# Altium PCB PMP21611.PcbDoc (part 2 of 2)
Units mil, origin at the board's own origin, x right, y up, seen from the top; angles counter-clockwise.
Board outline 4470 x 3145 mil, 4 copper layers (Top Layer, Signal Layer 1, Signal Layer 2, Bottom Layer), stack 60.6 mil thick; 95 components, 31 nets, 221 pads, 370 vias.
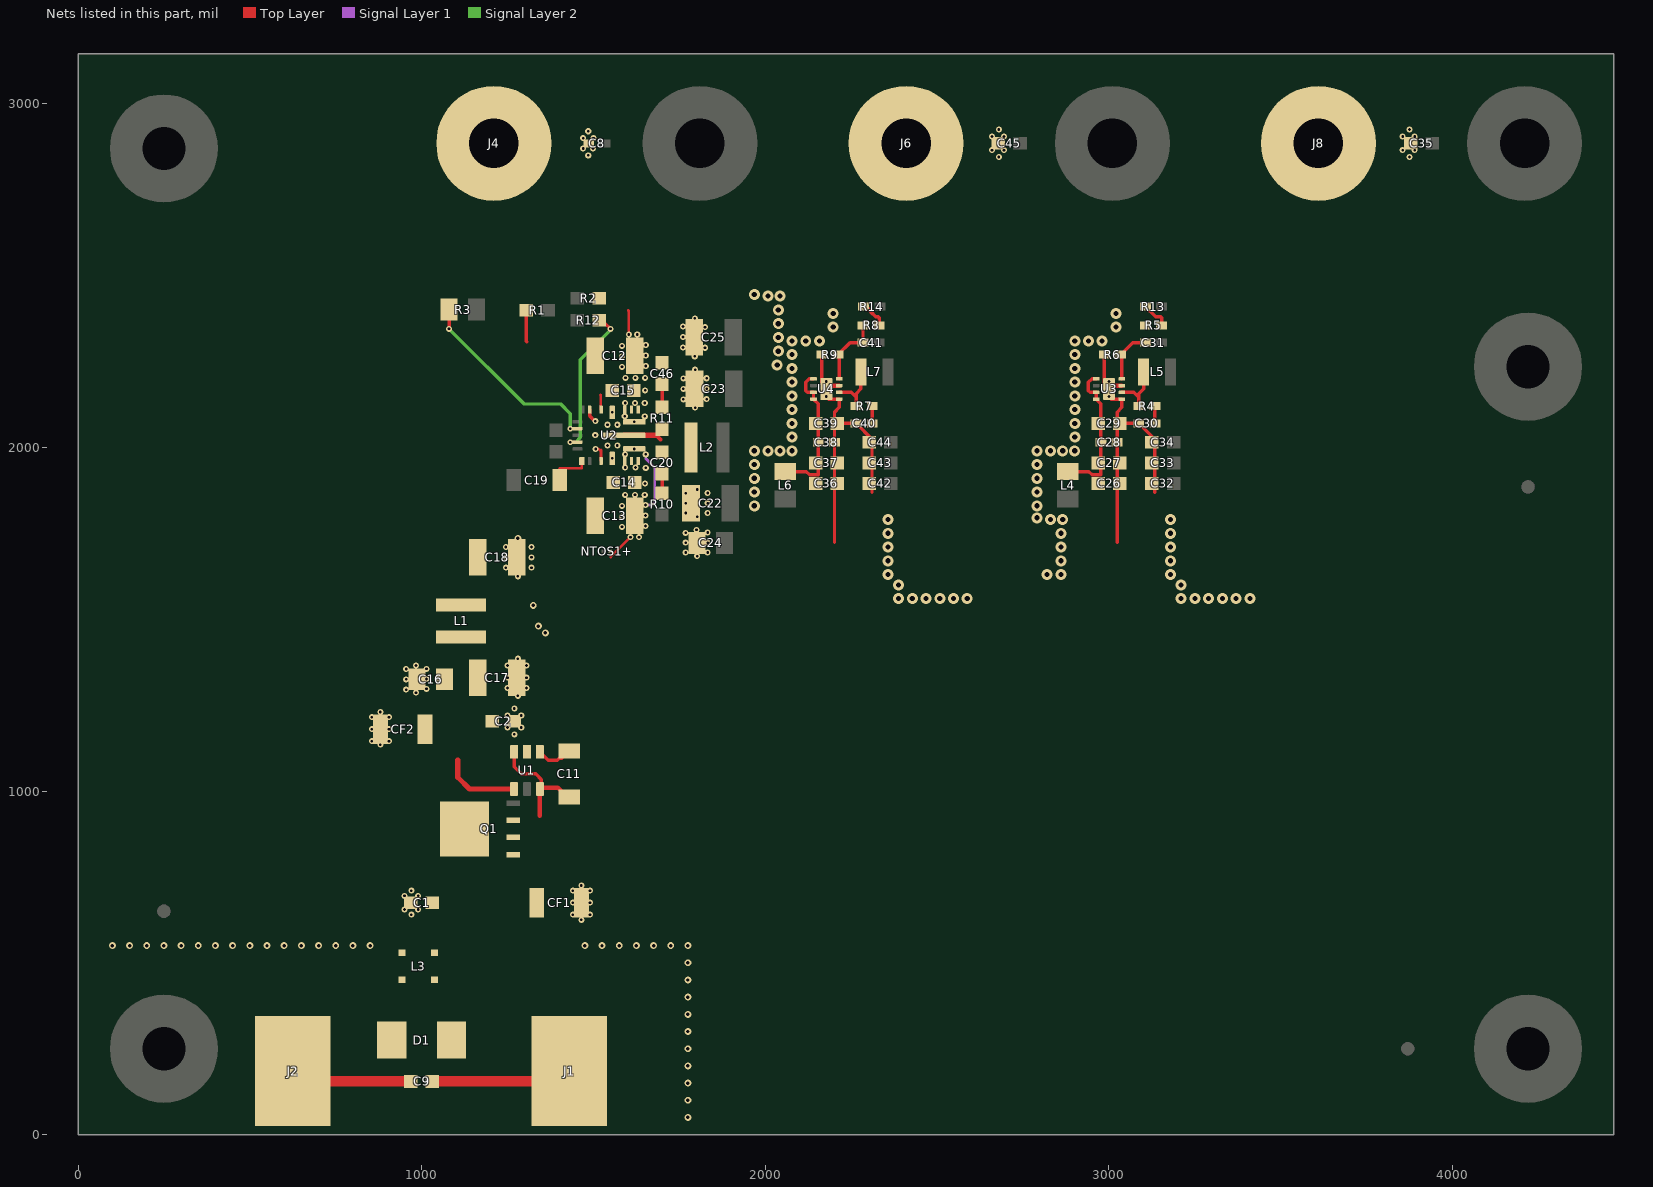
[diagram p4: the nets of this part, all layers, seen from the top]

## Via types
v1: diameter 32, hole 15, Top Layer to Bottom Layer, tented both sides, 156 vias
v2: diameter 17.72, hole 7.87, Top Layer to Bottom Layer, tented both sides, 150 vias
v3: diameter 20, hole 10, Top Layer to Bottom Layer, tented both sides, 45 vias
v4: diameter 17.72, hole 7.87, Top Layer to Bottom Layer, 9 vias
v5: diameter 15.75, hole 7.87, Top Layer to Bottom Layer, 5 vias
v6: diameter 19.68, hole 7.87, Top Layer to Bottom Layer, 4 vias
v7: diameter 15.75, hole 7.87, Top Layer to Bottom Layer, tented both sides, 1 vias

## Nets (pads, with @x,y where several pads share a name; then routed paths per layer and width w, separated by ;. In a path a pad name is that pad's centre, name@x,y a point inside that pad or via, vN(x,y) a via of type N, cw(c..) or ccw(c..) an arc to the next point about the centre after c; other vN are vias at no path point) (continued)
GND: C1.2 C2.2 C8.2 C12.2 C13.2 C14.2 C15.2 C16.2 C17.2 C18.2 C22.2 C23.2 C24.2 C25.2 C26.2 C27.2 C28.2 C29.2 C30.2 C32.2 C33.2 C34.2 C35.2 C36.2 C37.2 C38.2 C39.2 C40.2 C42.2 C43.2 C44.2 C45.2 C46.2 CF1.2 CF2.2 J4.1 J6.1 J8.1 L3.1 NTOS1+.2 R2.1 R6.1 R9.1 U1.2 U2.3 U2.5 U2.6 U2.7 U2.8 U2.10 U2.11 U2.12 U2.13 U2.16 U3.1 U3.3 U3.9@3000.55,2170 U4.1 U4.3 U4.9@2177.95,2170 | length 2267.3
  Top Layer w7.87: v2(1506.38,1995.38) 1514.57,1995.38 1521.77,1988.18 ; U2.3@1521.77,1960.2 1521.77,1988.18 ; 1521.77,1992.28 1521.77,1988.18 ; 1550.08,1680.83 v2(1607.99,1738.74) ; 1601.13,2399.17 1603.07,2397.23 v2(1603.07,2328.31)
  Top Layer w10: U2.16@1488.9,2109.8 1488.9,2091.4 1503.96,2076.34 v2(1505.63,2076.34) ; R9.1@2164.33,2270 2164.33,2183.62 U4.9@2177.95,2170 ; U4.9@2177.95,2154.25 U4.9@2177.95,2170 ; U4.9@2183.86,2179.84 2177.95,2185.75 U4.9@2177.95,2170 ; U4.9@2184.27,2147.94 2184.27,2140.47 U4.1@2215.35,2140.47 2215.35,2116.56 2201.57,2102.78 C39.2@2201.57,2070 ; 2201.57,1724.17 2201.57,1920 2201.57,1970 2201.57,2020 C39.2@2201.57,2070 ; 2310.71,1870 2310.71,1920 2310.71,1970 2310.71,2020 2310.71,2023.62 C40.2@2264.33,2070 C39.2@2201.57,2070 ; R6.1@2986.93,2270 2986.93,2183.62 U3.9@3000.55,2170 ; U3.9@3000.55,2154.25 U3.9@3000.55,2170 ; U3.9@3006.46,2179.84 3000.55,2185.75 U3.9@3000.55,2170 ; U3.9@3006.87,2147.94 3006.87,2140.47 U3.1@3037.95,2140.47 3037.95,2116.56 3024.17,2102.78 C29.2@3024.17,2070 ; 3024.17,1724.17 3024.17,1920 3024.17,1970 3024.17,2020 C29.2@3024.17,2070 ; 3133.31,1870 3133.31,1920 3133.31,1970 3133.31,2020 3133.31,2023.62 C30.2@3086.93,2070 C29.2@3024.17,2070
  Top Layer w13: U4.9@2183.86,2179.84 U4.3@2215.35,2179.84 ; U3.9@3006.46,2179.84 U3.3@3037.95,2179.84
  Top Layer w40: J4.1@1222.13,2755 J4.1@1223.95,2753.18
  Signal Layer 1 w8: v2(1651.3,1832.57) 1670,1832.57 1678.35,1840.92 1678.35,1941.65 1652.28,1967.72 v2(1652.28,1979.88)
  other v1: 2387.95,1560 2427.95,1560 2467.95,1560 2507.95,1560 2547.95,1560 2587.95,1560 3210.55,1560 3250.55,1560 3290.55,1560 3330.55,1560 3370.55,1560 3410.55,1560 2387.95,1600 3210.55,1600 2357.05,1630.02 2820.55,1630 2860.55,1630 3179.65,1630.02 2357.05,1670.02 2860.55,1670 3179.65,1670.02 2357.05,1710.02 2860.55,1710 3179.65,1710.02 2357.05,1750.02 2860.55,1750 3179.65,1750.02 2357.05,1790.02 2830.71,1790.16 2865.71,1790.16 3179.65,1790.02 2790.71,1795.16 1968.11,1830.16 2790.71,1830.16 1968.11,1870.16 2790.71,1870.16 1968.11,1910.16 2790.71,1910.16 1968.11,1950.16 2790.71,1950.16 1968.11,1990.16 2008.11,1990.16 2043.11,1990.16 2078.11,1990.16 2790.71,1990.16 2830.71,1990.16 2865.71,1990.16 2900.71,1990.16 2078.3,2030 2900.9,2030 2078.3,2070 2900.9,2070 2078.3,2110 2900.9,2110 2078.3,2150 2900.9,2150 2078.3,2190 2900.9,2190 2078.3,2230 2900.9,2230 2035,2240 2078.3,2270 2900.9,2270 2037.95,2280 2078.3,2310 2117.95,2310 2157.95,2310 2900.9,2310 2940.55,2310 2980.55,2310 2037.95,2320 2197.95,2350 3020.55,2350 2037.95,2360 2197.95,2390 3020.55,2390 2037.95,2400 2008.11,2440.16 2043.11,2440.16 1968.11,2445.16
  other v2: 1465,625 970,640 1440,640 1490,640 950,655 990,655 1440,675 1490,675 950,695 990,695 970,710 1440,710 1490,710 1465,725 880,1135 855,1145 905,1145 1270,1165 855,1180 905,1180 1250,1185 1290,1185 855,1215 905,1215 1250,1220 1290,1220 880,1230 1270,1240 1280,1276.85 983.87,1286.38 955,1295 1014.38,1297.2 1250,1300 1305,1300 955,1325 1014.38,1325.75 1250,1330 1305,1330 955,1355 1014.38,1355.43 983.87,1365.12 1250,1365 1305,1365 1280,1385 1280,1625 1245,1650 1320,1650 1245,1680 1320,1680 1801.93,1683.45 1768.46,1694.28 1832.44,1694.28 1245,1710 1320,1710 1768.46,1722.82 1832.44,1722.82 1632.6,1738.74 1768.46,1751.37 1832.44,1752.51 1800,1760 1583.39,1768.92 1651.3,1771.55 1801.93,1798.45 1583.39,1799.44 1651.3,1802.06 1768.46,1809.28 1832.44,1809.28 1583.39,1829.95 1768.46,1837.82 1832.44,1837.82 1592.22,1861.77 1620.77,1861.77 1649.31,1861.77 1768.46,1866.37 1832.44,1867.51 1801.93,1877.19 1650.31,1894.91 1592.24,1941.5 1622.76,1941.5 1652.28,1940.51 1592.24,1979.88 1541.06,2005.81 1569.61,2005.81 1505.4,2035.74 1541.06,2065.81 1569.61,2065.81 1649.33,2090.45 1591.26,2090.77 1796.02,2115.71 1592.24,2129.49 1620.79,2129.49 1649.33,2129.49 1761.57,2139.99 1829.49,2140.32 1650.47,2165.91 1761.57,2170.5 1761.57,2201.01 1829.49,2201.34 1593.39,2202.32 1621.93,2202.32 1650.47,2202.32 1796.02,2225.94 1583.39,2234.48 1652.28,2237.1 1583.39,2264.99 1795,2265 1652.28,2267.61 1825,2290 1760.83,2291 1583.39,2295.5 1652.28,2298.12 1760.83,2321.51 1627.68,2328.31 1825,2350 1760.83,2352.02 1795.28,2375.64 2680,2845 3875,2845 1485,2850 2660,2865 2695,2865 3855,2865 3890,2865 1470,2870 1498.94,2870 1470,2900 1500,2900 2660,2905 2695,2905 3855,2905 3890,2905 1485,2920 2680,2925 3875,2925
  other v3: 1775,50 1775,100 1775,150 1775,200 1775,250 1775,300 1775,350 1775,400 1775,450 1775,500 100,550 150,550 200,550 250,550 300,550 350,550 400,550 450,550 500,550 550,550 600,550 650,550 700,550 750,550 800,550 850,550 1475,550 1525,550 1575,550 1625,550 1675,550 1725,550 1775,550 1360,1460 1340,1480 1325,1540 1280,1735
  other v4: 1829.49,2170.83
  other v5: 1618.82,1995.63 1618.82,2074.37
  other v6: 2177.95,2148.35 3000.55,2148.35 2177.95,2191.65 3000.55,2191.65
NetC1_1: C1.1 C11.1 CF1.1 L3.4 Q1.1 Q1.2 Q1.3 U1.3 U1.6 | length 334.3
  Top Layer w10: U1.3@1269.29,1114.13 1269.29,1070.71 1290,1050 1331.69,1050 1348.23,1033.46 U1.6@1348.23,1010
  Top Layer w13: 1344.09,927.4 U1.6@1344.09,1005.87 1348.23,1010 1396.1,1010 C11.1@1425,981.1
NetC11_2: C11.2 U1.1 | length 107.1
  Top Layer w10: U1.1@1344.09,1114.13 1368.23,1090 1395,1090 1400,1095 1408.07,1095 C11.2@1430,1116.93
NetC19_1: C19.1 U2.1 | length 105.7
  Top Layer w7.87: C19.1@1387.52,1923.78 1402.68,1938.94 1465.67,1938.94 U2.1@1465.67,1960.2
NetC20_2: C20.2 R10.2 | length 62.8
  Top Layer w10: R10.2@1700,1863.62 C20.2@1700,1926.38
NetC26_1: C26.1 C27.1 C28.1 C29.1 L4.2 U3.5 U3.7 U3.8 | length 432.6
  Top Layer w10: L4.2@2880.71,1929.53 2942.18,1929.53 2951.71,1920 2976.93,1920 2976.93,1970 2976.93,2020 2976.93,2070 2976.93,2126.69 U3.8@2963.15,2140.47 U3.7@2963.15,2160.16 2945.75,2160.16 2940.43,2165.47 2940.43,2189.04 2951.34,2199.95 U3.5@2962.73,2199.95 ; 2951.86,2199.53 U3.5@2963.15,2199.53
NetC30_1: C30.1 R4.1 | length 50
  Top Layer w10: C30.1@3134.17,2070 R4.1@3134.17,2120
NetC31_2: C31.2 R5.1 R6.2 U3.4 | length 159
  Top Layer w10: U3.4@3037.95,2199.53 3037.95,2266.22 R6.2@3034.17,2270 3069.17,2305 C31.2@3106.38,2305 ; R5.1@3106.93,2350 R5.1@3107.09,2349.84
NetC36_1: C36.1 C37.1 C38.1 C39.1 L6.2 U4.5 U4.7 U4.8 | length 432.6
  Top Layer w10: L6.2@2058.11,1929.53 2119.58,1929.53 2129.11,1920 2154.33,1920 2154.33,1970 2154.33,2020 2154.33,2070 2154.33,2126.69 U4.8@2140.55,2140.47 U4.7@2140.55,2160.16 2123.15,2160.16 2117.83,2165.47 2117.83,2189.04 2128.75,2199.95 U4.5@2140.13,2199.95 ; 2129.26,2199.53 U4.5@2140.55,2199.53
NetC40_1: C40.1 R7.1 | length 50
  Top Layer w10: C40.1@2311.57,2070 R7.1@2311.57,2120
NetC41_2: C41.2 R8.1 R9.2 U4.4 | length 204.4
  Top Layer w10: U4.4@2215.35,2199.53 2215.35,2266.22 R9.2@2211.57,2270 2246.73,2305.16 2284.49,2305.16 2284.49,2349.84 R8.1@2284.33,2350
NetC46_1: C46.1 R11.2 | length 67
  Top Layer w10: R11.2@1700,2116.5 C46.1@1700,2183.5
NetL5_1: L5.1 R4.2 U3.2 | length 160.6
  Top Layer w10: U3.2@3037.95,2160.16 3073.05,2160.16 3086.93,2146.28 ; R4.2@3086.93,2120 3086.93,2146.28 ; L5.1@3101.18,2220 3101.18,2170.51 3086.93,2156.26 3086.93,2146.28
NetL7_1: L7.1 R7.2 U4.2 | length 160.6
  Top Layer w10: U4.2@2215.35,2160.16 2250.45,2160.16 2264.33,2146.28 ; R7.2@2264.33,2120 2264.33,2146.28 ; L7.1@2278.58,2220 2278.58,2170.51 2264.33,2156.26 2264.33,2146.28
NetR5_2: R5.2 R13.1 | length 82.8
  Top Layer w10: R13.1@3106.38,2410 3136.38,2380 3150.5,2380 3153.62,2376.88 R5.2@3153.62,2355
NetR8_2: R8.2 R14.1 | length 81.7
  Top Layer w10: R14.1@2286.38,2410 2293.19,2410 2307.87,2395.31 2307.87,2394.05 2321.92,2380 2328.61,2380 2331.73,2376.88 R8.2@2331.73,2355
NetR12_1: R12.1 U2.21 | length 455.7
  Top Layer w7.87: v5(1432.79,2015.31) U2.21@1453.46,2015.31
  Top Layer w10: R12.1@1508.62,2360 1535,2360 v2(1550,2345)
  Signal Layer 2 w10: v5(1432.79,2015.31) 1448.58,2015.31 1462.13,2028.86 1462.13,2255 1550,2342.87 v2(1550,2345)
RS1: R3.1 U2.19 | length 575.8
  Top Layer w7.87: v7(1432.79,2054.68) U2.19@1453.46,2054.68
  Top Layer w10: v2@1079.8,2345.04 R3.1@1079.8,2401.14
  Signal Layer 2 w10: v2(1079.45,2345.04) 1298.2,2126.29 1404.5,2126.29 1432.79,2097.99 v7(1432.79,2054.68)
SW1: C20.1 L2.1 R11.1 U2.9 | length 111.2
  Top Layer w11.81: R11.1@1683.78,2035 1695.59,2023.19
  Top Layer w15.75: U2.9@1589.29,2035 R11.1@1683.78,2035
"VBATT +": C9.1 D1.1 J1.1 L3.3 | length 410.9
  Top Layer w30: C9.1@1031.5,155 1400,155 J1.1@1430,185
"VBATT -": C9.2 D1.2 J2.1 L3.2 | length 355.9
  Top Layer w30: J2.1@625,185 655,155 C9.2@968.5,155
VIN: C2.1 C16.1 C17.1 CF2.1 L1.1 Q1.5 U1.4 | length 228.4
  Top Layer w15: 1105,1090 1105,1040 1139.13,1005.87 U1.4@1269.29,1005.87
VIN1: C12.1 C13.1 C14.1 C15.1 C18.1 L1.2 R1.2 U2.4 U2.14 U2.15 | length 136.3
  Top Layer w7.87: 1520.39,2152.78 1521.38,2151.8 1521.38,2110.2 U2.15@1521.77,2109.8
  Top Layer w10: R1.2@1304.84,2399.17 1304.84,2308.62 1305.83,2307.64 ; U2.14@1554.84,2109.8 U2.14@1555.44,2110.4
  other v5: 1554.84,1968.07 1554.84,2101.93
pads on no net: FID1.1 FID2.1 FID3.1 FID4.1 FID5.1 FID6.1 H1.1 H2.1 H3.1 H4.1 H5.0 H6.0 H7.0 H8.0 U2.4A U2.4B U2.8A U2.8B U2.9A U2.9B U2.9C U2.9D U2.10A U2.10B U2.14A U2.14B U2.17 U3.6 U3.9@3000.55,2152.28 U3.9@3000.55,2187.72 U4.6 U4.9@2177.95,2152.28 U4.9@2177.95,2187.72

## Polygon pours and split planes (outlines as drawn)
NetC31_2 on Top Layer "TOP_LAYER_NETC31_2_P226" (solid, remove dead copper, pour order 226): 3028.01,2194.2 3028.01,2247.9 3018.71,2257.19 3018.71,2290.59 3090.24,2362.13 3123.64,2362.13 3123.64,2293.44 3079.83,2293.44 3051.55,2265.16 3051.55,2194.2
GND on Top Layer "TOP_LAYER_GND_P236" (solid, remove dead copper, pour order 236): 3003.86,1672.66 3003.86,1747.66 3058.86,1747.66 3058.86,1672.66
NetL5_1 on Top Layer "TOP_LAYER_NETL5_1_P224" (solid, remove dead copper, pour order 224): 3081.55,2265.16 3121.55,2265.16 3121.55,2165.16 3101.55,2145.16 3101.55,2105.16 3071.55,2105.16 3071.55,2265.16
NetC26_1 on Top Layer "TOP_LAYER_NETC26_1_P220" (solid, remove dead copper, pour order 220): 2816.55,1895.16 2991.55,1895.16 2991.55,2125.16 2971.55,2145.16 2971.55,2205.16 2951.55,2205.16 2951.55,1955.16 2816.55,1955.16
+5V on Top Layer "TOP_LAYER_+5V_P214" (solid, remove dead copper, pour order 214): 2941.55,1488 2991.55,1488 2991.55,1885.16 2816.55,1885.16 2816.55,1825.16 2941.55,1825.16
+3.3V on Top Layer "TOP_LAYER_+3.3V_P212" (solid, remove dead copper, pour order 212): 3410.55,2450 3136.55,2450 3136.55,2285.16 3160.55,2285.16 3160.55,1850 3231.55,1850 3231.55,1635.16 3410.55,1635.16
+3.3V on Top Layer "TOP_LAYER_+3.3V_P210" (solid, remove dead copper, pour order 210): 3410.55,2361.92 3136.55,2361.92 3136.55,2285.16 3160.55,2285.16 3160.55,1850 3231.55,1850 3231.55,1635.16 3410.55,1635.16
+5V on Top Layer "TOP_LAYER_+5V_P200" (solid, remove dead copper, pour order 200): 2118.95,1490 2168.95,1490 2168.95,1880.16 1993.95,1880.16 1993.95,1820.16 2118.95,1820.16
+1.2V on Top Layer "TOP_LAYER_+1.2V_P196" (solid, remove dead copper, pour order 196): 2587.95,2420 2313.95,2420 2313.95,2285.16 2337.95,2285.16 2337.95,1850 2408.95,1850 2408.95,1635.16 2587.95,1635.16
NetC36_1 on Top Layer "TOP_LAYER_NETC36_1_P194" (solid, remove dead copper, pour order 194): 1993.95,1895.16 2168.95,1895.16 2168.95,2125.16 2148.95,2145.16 2148.95,2205.16 2128.95,2205.16 2128.95,1955.16 1993.95,1955.16
NetL7_1 on Top Layer "TOP_LAYER_NETL7_1_P192" (solid, remove dead copper, pour order 192): 2258.95,2265.16 2298.95,2265.16 2298.95,2165.16 2278.95,2145.16 2278.95,2105.16 2248.95,2105.16 2248.95,2265.16
GND on Top Layer "TOP_LAYER_GND_P242" (solid, remove dead copper, pour order 242): 2181.26,1672.66 2181.26,1747.66 2236.26,1747.66 2236.26,1672.66
NetC41_2 on Top Layer "TOP_LAYER_NETC41_2_P190" (solid, remove dead copper, pour order 190): 2205.41,2194.2 2205.41,2247.9 2196.11,2257.19 2196.11,2290.59 2267.65,2362.13 2301.04,2362.13 2301.04,2293.44 2257.23,2293.44 2228.95,2265.16 2228.95,2194.2
+1.2V on Top Layer "TOP_LAYER_+1.2V_P188" (solid, remove dead copper, pour order 188): 2587.95,2361.92 2313.95,2361.92 2313.95,2285.16 2337.95,2285.16 2337.95,1850 2408.95,1850 2408.95,1635.16 2587.95,1635.16
NetC26_1 on Top Layer "TOP_LAYER_NETC26_1_P228" (solid, remove dead copper, pour order 228): 3052,1904 2817,1904 2817,1980.99 2717,1980.99 2717,2703.5 3052,2703.5
+1.2V on Top Layer "TOP_LAYER_+1.2V_P232" (solid, remove dead copper, pour order 232): 2408.95,1635.16 2408.95,1850 2342.2,1850 2337.95,1854.25 2342.2,2430.5 2588.95,2430.5 2588.95,2398.95 2588.95,1636.16 2587.95,1635.16
GND on Top Layer "TOP_LAYER_GND_P238" (solid, remove dead copper, pour order 238): 0,3145 4445,3145 4445,-0.49 0,-0.49
GND on Signal Layer 1 "SIGNAL_LAYER_1_GND_P250" (solid, remove dead copper, pour order 250): -0.49,3160.57 4469.51,3160.57 4469.51,15.57 -0.49,15.57
GND on Signal Layer 2 "SIGNAL_LAYER_2_GND_P254" (solid, remove dead copper, pour order 254): -15,3795 4475,3795 4475,0 -15,0
GND on Bottom Layer "BOTTOM_LAYER_GND_P260" (solid, remove dead copper, pour order 260): 5,3145 4470,3145 4470,0 5,0
+1.2V on Bottom Layer "BOTTOM_LAYER_+1.2V_P256" (solid, remove dead copper, pour order 256): 2587.95,2430 2313.95,2430 2313.95,2285.16 2337.95,2285.16 2337.95,1850 2408.95,1850 2408.95,1635.16 2587.95,1635.16
+3.3V on Bottom Layer "BOTTOM_LAYER_+3.3V_P258" (solid, remove dead copper, pour order 258): 3410.55,2450 3136.55,2450 3136.55,2285.16 3160.55,2285.16 3160.55,1850 3231.55,1850 3231.55,1635.16 3410.55,1635.16

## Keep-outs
Keep-Out Layer:
  lines w10: -5.93,3145 0.18,0 4476.12,0 4470,3145 -5.93,3145
  text ".Layer_Name" at -33,-1358.49 h60

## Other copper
Top Layer:
  rectangle net NetC1_1: 1245,580 1380,935
  rectangle net NetC1_1: 1015,505 1380,765
  rectangle net +3.3V: 3915,2655 4445,3120
  rectangle net +1.2V: 2720,2655 3255,3120
  rectangle net +5V: 1515,2655 2050,3120
  rectangle net GND: 3098,2039 3111,2051
  rectangle net SW1: 1707,1972 1738,2062
  rectangle net +5V: 1905,1345 3000,1520
  rectangle net GND: 1500.71,1984.8 1537.61,2016.96
  region net GND: 1500.71,2016.96 1500.71,1997.27 1657.2,1997.27 1657.2,2016.96
  region net VIN1: 1200,2217.09 1200,2107.83 1403.27,2107.83 1403.27,2217.09
  rectangle net GND: 1811.89,2221.47 1843.39,2337.94
  rectangle net GND: 1810.79,2111.44 1831.46,2227.91
  rectangle net SW1: 1730.04,1927.39 1805,2073.06
  rectangle net +5V: 1852.72,1345 1945,2401.14
  region net VIN1: 1514.49,1916.89 1514.49,1749.57 1543.03,1749.57 1543.03,1916.89
  region net VIN1: 1507.6,2184.61 1507.6,2138.35 1564.68,2138.35 1564.68,2184.61
  region net VIN1: 1440,1916.89 1440,1750.55 1565,1750.55 1565,1916.89
  region net VIN1: 1025,1855 1025,1750 1525.31,1750 1525.31,1855
  region net GND: 1590.28,2004.16 1590.28,1923.78 1663.11,1923.78 1663.11,2004.16
  region net VIN1: 1538.11,2184.61 1538.11,2097.01 1572.56,2097.01 1572.56,2184.61
  region net VIN1: 1149.33,2317.48 1149.33,2176.73 1560.75,2176.73 1560.75,2317.48
  region net VIN1: 1025,2317.48 1025,1825 1235,1825 1235,2317.48
  region net GND: 1673.94,2418.18 1591.26,2418.18 1591.26,2062.23 1673.94,2062.23
  region net VIN1: 1541.06,1973.98 1541.06,1881.46 1572.56,1881.46 1572.56,1973.98
  region net AGND1: 1298.94,2091.1 1298.94,1961.84 1357.99,1961.84 1357.99,2091.1
  region net AGND1: 1339.29,2090.77 1339.29,2024.17 1410.16,2024.17 1410.16,2090.77
  region net GND: 1502.68,2076.67 1502.68,1995.63 1513.5,1995.63 1513.5,2076.67
  region net GND: 1505.63,2073.06 1505.63,2051.4 1657.2,2051.4 1657.2,2073.06
  rectangle net SW1: 1679.84,1995 1760,2050.42
  rectangle net GND: 1590.28,1674.76 1663.11,1923.78
  rectangle net GND: 1548,1670.42 1661.14,1727.91
  rectangle net AGND1: 1300,1875 1345.2,1994.32
  rectangle net VIN1: 1530.24,2174.44 1571.57,2211.84
  rectangle net GND: 1003.56,1297.2 1023.56,1354.29
  rectangle net GND: 1820.35,1805.81 1840.35,1875.81
  rectangle net GND: 1263.62,1627.43 1318.62,1733.25
  rectangle net GND: 1825.35,2135.81 1840.35,2210.81
  rectangle net GND: 1575.35,1767.03 1590.28,1835.81
  rectangle net GND: 1482.99,1984.48 1505.63,2124.24
  rectangle net AGND1: 1245,1875 1346.18,1935
  rectangle net VIN1: 1220,1950 1290,2160
  rectangle net VIN1: 1025,1516.23 1190,1785
  rectangle net VIN: 1040,1110 1190,1465
  region net "VBATT +": 1575,25 1575,475 1572.28,472.28 1015.59,472.28 1015.59,215.59 1015,215 1070,215 1070,25
  region net "VBATT -": 475,25 475,475 970,475 970,215 930,215 935,210 935,25
  region net +5V: 1830,2980 1830,2365 2005,2365 2005,2415 1945.64,2415 1945.64,2980
  pour cut-out: 3061.55,1730.16 3061.55,2020.16 3096.55,2020.16 3096.55,1730.16
  pour cut-out: 2238.95,1730.16 2238.95,2020.16 2273.95,2020.16 2273.95,1730.16
  pour cut-out: 1471.18,2134.08 1579.45,2134.08 1579.45,1954.98 1549.92,1925.45 1547.99,1927.39 1471.18,1927.39
  pour cut-out: 1590.28,2336.18 1590.28,2091.1 1592.24,2089.13 1588.31,2085.2 1573.54,2085.2 1573.54,2315.31 1571.38,2317.48 1150.31,2317.48 1150.31,2333.23 1153.27,2336.18
  pour cut-out: 1590.28,1736.77 1590.28,1727.91 1562.72,1727.91 1532.2,1727.91 1501.69,1727.91 1464.29,1727.91 1464.29,1810.59 1472.16,1818.46 1473.15,1817.48 1482.99,1817.48 1482.99,1750.55 1572.56,1750.75 1572.56,1981.85 1575.51,1984.8 1590.28,1984.8
  region net VIN1: 1454.45,2136.38 1507.6,2136.38 1539.09,2136.38 1539.09,2174.26 1468.24,2197.54 1453.16,2185.36 1454.45,2178.37 1454.45,2171.48
  pour cut-out: 1736.93,2059.61 1736.93,2004.49 1517.83,2004.49 1517.44,2004.88 1517.44,2059.61
  pour cut-out: 1800.74,2022.75 1805,2022.75 1805,1966.1 1745.5,1966.1 1745.5,2022.75
  pour cut-out: 1820,2084.87 1674.92,2084.87 1645.39,2055.34 1530.24,2055.34 1520.39,2045.5 1520.39,2025.81 1530.24,2015.97 1658.19,2015.97 1658.19,1976.91 1680.09,1955 1720.5,1955 1720.5,1914.59 1739.88,1914.59 1820,1914.59
  pour cut-out: 1874.72,2083.88 1904.85,2083.88 1905,2083.74 1905,1910 1875,1910
  region net VIN: 980,1245 1225,1245 1225,786.06 980,786.06
  pour cut-out: 0,0 1750,0 1750,505 0,505
Signal Layer 1:
  region net AGND1: 1301.89,2092.74 1301.89,1963.81 1357.01,1963.81 1357.01,2092.74
  pour cut-out: 2408.95,1640.16 2588.95,1640.16 2588.95,2335.33 2408.95,2335.33
  pour cut-out: 3231.55,1640.16 3411.55,1640.16 3411.55,2335.33 3231.55,2335.33
  pour cut-out: 1820,2084.5 1674.92,2084.5 1645.39,2054.97 1530.24,2054.97 1520.39,2045.13 1520.39,2025.44 1530.24,2015.6 1658.19,2015.6 1658.19,1976.54 1679.73,1955 1720.5,1955 1720.5,1914.22 1739.88,1914.22 1820,1914.22
  pour cut-out: 0,0 1750,0 1750,505 0,505
Signal Layer 2:
  region net AGND1: 1301.89,2092.74 1301.89,1963.81 1357.01,1963.81 1357.01,2092.74
  rectangle net GND: 1750,2105 1845,2350
  rectangle net GND: 1570,1715 1665,1905
  rectangle net GND: 1813.32,1785 1910,1885.84
  pour cut-out: 2408.95,1640.16 2588.95,1640.16 2588.95,2335.33 2408.95,2335.33
  pour cut-out: 3231.55,1640.16 3411.55,1640.16 3411.55,2335.33 3231.55,2335.33
  pour cut-out: 1820,2084.5 1674.92,2084.5 1645.39,2054.97 1530.24,2054.97 1520.39,2045.13 1520.39,2025.44 1530.24,2015.6 1658.19,2015.6 1658.19,1976.54 1679.72,1955 1720.5,1955 1720.5,1914.22 1739.88,1914.22 1820,1914.22
  pour cut-out: 0,0 1750,0 1750,505 0,505
Bottom Layer:
  rectangle net +3.3V: 3915,2655 4445,3120
  rectangle net +1.2V: 2720,2655 3255,3120
  rectangle net +5V: 1515,2655 2050,3120
  region net AGND1: 1301.89,2092.74 1301.89,1963.81 1357.01,1963.81 1357.01,2092.74
  pour cut-out: 0,0 1750,0 1750,505 0,505

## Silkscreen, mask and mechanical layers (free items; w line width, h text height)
Top Overlay:
  region: 3390,334 3090,334 3090,234 3390,234
  text "GND" at 1200,2555 h60
  text "+5V" at 1750,2555 h60
  text "+1.2V" at 2845,2555 h60
  text "GND" at 3530,2555 h60
  text "GND" at 2365,2550 h60
  text "+3.3V" at 4120,2545 h40
  text "1" at 1451.5,1929.68 h19.68 r270
  text "-" at 940,1070 h78.74 r180
  text "+" at 1139.13,1005.87 h78.74 r90
  text "'.PRJ_Number' '.PCB_Rev'" at 2370,250 h108.27
Top Solder:
  rectangle: 1516,1934 1525,1955
  rectangle: 125,150 310,370
Bottom Solder:
  rectangle: 1475.53,2149.07 1486,2159.54
Drill Guide:
  text ".Layer_Name" at -33,-1358.49 h60
M1 Board Outline:
  the board outline again, w10
  text ".Layer_Name" at -33,-1358.49 h60
M2 Board Dimensions:
  rectangle: -485,-900 -110,-775
  rectangle: -610,-775 -485,-650
  lines w7: -610,-775 390,-775 ; -485,-900 -485,-650 ; -360,-900 -360,-650 ; -110,-900 -110,-650 ; 140,-900 140,-650 ; -610,-900 -610,-650 390,-650 390,-900 -610,-900
  text ".Layer_Name" at -33,-1358.49 h60
M3 3D STEP Top:
  text ".Layer_Name" at -33,-1358.49 h60
M4 3D STEP Bottom:
  text ".Layer_Name" at -33,-1358.49 h60
M5 Assembly Top:
  lines w10: -902,-1430.17 5698,-1430.17 ; -902,-1226.83 5700,-1226.83 ; -902,-1023.5 -902,-1633.5 3103,-1633.5 5700,-1633.5 5700,-1023.5 -901.5,-1023.5 -901.5,-1633.5 674,-1633.5 ; 1563,-1633.5 1563,-1023.5 ; 2830,-1226.83 2830,-1023.5 ; 3670,-1226.83 3670,-1023.5 ; 4292,-1640 4292,-1437.17
  text "COMPONENTS MARKED 'DNP' SHOULD NOT BE POPULATED." at 543.5,-818.5 h60
  text "ASSEMBLY VARIANT:" at 543,-934 h60
  text ".VariantName" at 1579,-934 h60
  text "PCB VIEWED FROM TOP SIDE" at -838.5,-1155.67 h60
  text "BOARD #:" at 1638,-1155.67 h60
  text ".PRJ_Number" at 2183.5,-1155.67 h60
  text "REV:" at 3028,-1155.67 h60
  text ".PCB_Rev" at 3319.5,-1155.67 h60
  text "SVN REV:" at 3866,-1155.67 h60
  text ".VersionControl_RevNumber" at 4372,-1155.67 h60
  text "TID #:" at 1638,-1359 h60
  text ".TID" at 2183.5,-1359 h60
  text "PLOT NAME =" at -838.5,-1564.34 h60
  text ".plot_File_Name" at -33,-1564.34 h60
  text "GENERATED    :" at 1640,-1564.34 h60
  text ".Print_Date" at 2509.5,-1564.34 h60
  text ".Print_Time" at 3238.5,-1564.34 h60
  text "TEXAS INSTRUMENTS" at 4503,-1564.34 h60
M6 Assembly Bottom:
  lines w10: -902.5,-1227.33 5699.5,-1227.33 ; -900.5,-1430.67 5699.5,-1430.67 ; 505.5,-1640.5 505.5,-1437.67 ; 1127.5,-1227.33 1127.5,-1024 ; 1967.5,-1227.33 1967.5,-1024 ; 3234.5,-1634 3234.5,-1024 ; 4123.5,-1634 5699,-1634 5699,-1024 -902.5,-1024 -902.5,-1634 1694.5,-1634 5699.5,-1634 5699.5,-1024
  text "COMPONENTS MARKED 'DNP' SHOULD NOT BE POPULATED." at 5492,-818 h60
  text ".VariantName" at 4448,-934 h60
  text "ASSEMBLY VARIANT:" at 5487,-934 h60
  text ".VersionControl_RevNumber" at 425.5,-1156.17 h60
  text "SVN REV:" at 931.5,-1156.17 h60
  text ".PCB_Rev" at 1478,-1156.17 h60
  text "REV:" at 1769.5,-1156.17 h60
  text ".PRJ_Number" at 2614,-1156.17 h60
  text "BOARD #:" at 3159.5,-1156.17 h60
  text "PCB VIEWED FROM BOTTOM SIDE" at 5636,-1156.17 h60
  text ".TID" at 2614,-1359.5 h60
  text "TID #:" at 3159.5,-1359.5 h60
  text "TEXAS INSTRUMENTS" at 294.5,-1564.84 h60
  text ".Print_Time" at 1559,-1564.84 h60
  text ".Print_Date" at 2288,-1564.84 h60
  text "GENERATED    :" at 3157.5,-1564.84 h60
  text ".plot_File_Name" at 4830.5,-1564.84 h60
  text "PLOT NAME =" at 5636,-1564.84 h60
M9 Title Sheet:
  drawing of 57 lines, arcs and shapes, not listed
  text "1" at 129.84,7536.5 h70
  text "2" at 2625.5,7536.5 h70
  text "3" at 5114.84,7536.5 h70
  text "4" at 7621.51,7536.5 h70
  text "5" at 10120.5,7536.5 h70
  text "6" at 12625.5,7536.5 h70
  text "A" at -1026.5,6393.5 h70
  text "A" at 13773.5,6393.5 h70
  text "B" at -1026.5,4013.5 h70
  text "B" at 13773.5,4013.5 h70
  text "C" at -1026.5,1638.5 h70
  text "C" at 13773.5,1638.5 h70
  text ".PRJ_Title" at 10783.5,-355.83 h70
  text "DESIGNED FOR:" at 10733.5,-523.5 h45
  text ".PRJ_Customer" at 10783.5,-663.5 h70
  text "D" at -1026.5,-731.5 h70
  text "D" at 13773.5,-731.5 h70
  text "FILE NAME:" at 10733.5,-823.5 h45
  text ".PCB_File_Name_No_Path" at 10783.5,-943.5 h70
  text "Texas Instruments (TI) and/or its licensors do not warrant the accuracy or completeness of this specification" at 5764,-1105.34 h45
  text "ENGINEER:" at 10733.5,-1113.5 h45
  text "LAYOUT BY:" at 12238.5,-1113.5 h45
  text "or any information contained therein. TI and/or its licensors do not warrant that this design will meet" at 5719.01,-1218 h45
  text ".PRJ_Engineer" at 10783.5,-1268.49 h70
  text ".PCB_Layout" at 12289,-1268.49 h70
  text "the specifications, will be suitable for your application or fit for any particular purpose, or will operate in" at 5719.01,-1330.67 h45
  text ".Layer_Name" at -33,-1358.49 h60
  text "ALTIUM DESIGNER VERSION:" at 12238.5,-1423.5 h45
  text "an implementation. TI and/or its licensors do not warrant that the design is production worthy. You should" at 5719.01,-1443.33 h45
  text "completely validate and test your design implementation to confirm the system functionality for your application." at 5764,-1556 h45
  text ".print_Scale" at 10783.5,-1556.83 h70
  text ".Application_BuildNumber" at 12289,-1556.83 h70
  text "1" at 129.84,-1763.5 h70
  text "2" at 2625.5,-1763.5 h70
  text "3" at 5114.84,-1763.5 h70
  text "4" at 7621.51,-1763.5 h70
  text "5" at 10120.5,-1763.5 h70
  text "6" at 12625.5,-1763.5 h70
M10 Fab Notes:
  drawing of 189 lines, arcs and shapes, not listed
  text "DESIGN INFORMATION" at 11772.02,5856.17 h60
  text "MIN. TRACK WIDTH:" at 11127.46,5724.05 h60
  text "8" at 12223.7,5724.05 h60
  text "MIL" at 12378.46,5724.05 h60
  text "MIN. CLEARANCE:" at 11127.46,5599.92 h60
  text "0.2" at 12163.7,5599.93 h60
  text "mm" at 12378.46,5599.92 h60
  text "15.748" at 12000,5485 h60
  text "MIN. VIA PAD SIZE:" at 11127.46,5475.8 h60
  text "MIL" at 12378.46,5475.8 h60
  text "0.05mm (2MIL)" at 11822.46,5345.9 h60
  text "MINIMUM ANNULAR RING" at 10798.23,5337.67 h60
  text "EXTERNAL" at 12530.46,5337.67 h60
  text "PER" at 10998.23,5227.55 h60
  text "IPC-D-275 CLASS 2 LEVEL C" at 11218.23,5227.54 h60
  text "MIL, HOLES" at 12706.46,5127.07 h60
  text "+/-" at 12314,5118.48 h60
  text "+/-" at 13168,5118.48 h60
  text "REGISTRATION TOLERANCES:" at 10798.23,5117.42 h60
  text "METAL" at 11998,5117.42 h60
  text "5" at 12574.2,5117.42 h60
  text "3" at 13407.2,5117.42 h60
  text "MIL" at 13523.46,5117.42 h60
  text "HOLE SIZE TOLERANCE (UNLESS OTHERWISE SPECIFIED):" at 10798.23,5019.1 h60
  text "+/-" at 13168,5016.23 h60
  text "3" at 13407.2,5015.17 h60
  text "MIL" at 13523.46,5015.17 h60
  text "MATERIAL:" at 10723.46,4877.52 h60
  text "FR-4 High Tg" at 11709.9,4749 h60
  text "X" at 11565.46,4741.01 h60
  text "FR-408" at 11144.46,4736.49 h60
  text "OTHER" at 12632.46,4736.49 h60
  text "62 MIL (1.6mm) +/-10%" at 11464.56,4593.46 h60
  text "X" at 11344.46,4591.01 h60
  text "THICKNESS:" at 10798.23,4585.24 h60
  text "OTHER" at 12749.46,4585.24 h60
  text "TOLERANCE:" at 10798.23,4446.92 h60
  text "X" at 11646.46,4446.92 h60
  text "ANSI IPC-6012 TYPE 3 CLASS 2" at 11824.48,4446.92 h60
  text "OTHER +/-" at 11824.46,4302.73 h60
  text "BOW & TWIST:" at 10798.23,4157.54 h60
  text "X" at 11646.46,4157.54 h60
  text "ANSI IPC-6012 TYPE 3 CLASS 2" at 11824.48,4157.54 h60
  text "OTHER +/-" at 11824.46,4010.85 h60
  text "DRILLING:" at 10723.46,3880.23 h60
  text "NC_DRILL FILES" at 12484.46,3775.04 h60
  text "REFERENCE:" at 10798.23,3771.1 h60
  text "X" at 11455.46,3771.01 h60
  text "AS SHOWN" at 11633.46,3771.1 h60
  text "X" at 12356.46,3771.1 h60
  text "OTHER" at 12782.46,3628.85 h60
  text "PTH COPPER THICKNESS:" at 10797.91,3625.32 h60
  text "X" at 11937.14,3625.32 h60
  text "20-30 um" at 12065.14,3625.32 h60
  text "BOARD FINISH:" at 10723.46,3477.73 h60
  text "SILKSCREEN:" at 10878.68,3367.6 h60
  text "X" at 11836.46,3367.6 h60
  text "TOP" at 11953.46,3367.6 h60
  text "X" at 12346.46,3367.6 h60
  text "BOTTOM" at 12464.46,3367.6 h60
  text "SILKSCREEN COLOR:" at 10878.68,3212.41 h60
  text "X" at 11835.46,3212.41 h60
  text "WHITE" at 11953.46,3212.41 h60
  text "OTHER" at 12464.46,3212.41 h60
  text "X" at 11966.46,3068.96 h60
  text "GREEN" at 12084.46,3068.96 h60
  text "OTHER" at 12702.46,3068.96 h60
  text "SOLDER RESIST COLOR:" at 10878.68,3062.1 h60
  text "X" at 11966.46,2914.71 h60
  text "MATTE" at 12084.46,2914.71 h60
  text "SEMI-GLOSS" at 12702,2914.07 h60
  text "IMMERSION GOLD (ENIG)" at 11784.46,2741.94 h60
  text "ENEPIG" at 13122,2734.72 h60
  text "SURFACE FINISH:" at 10723.46,2733.72 h60
  text "X" at 11606.46,2733.72 h60
  text "IMM. TIN/SILVER OR EQUIV" at 11053,2596.4 h60
  text "OTHER" at 12484.46,2592.47 h60
  text "ARRAY/PANEL:" at 10723.46,2437.09 h60
  text "X" at 11610,2430 h60
  text "CUT AND TRIM PER M1 BOARD OUTLINE" at 11784.46,2428.87 h60
  text "N.C. ROUTE" at 11784.46,2292.9 h60
  text "V. SCORE" at 12650.46,2292.9 h60
  text "CERTIFICATION:" at 10723.46,2163.77 h60
  text "MATERIALS AND WORKMANSHIP FOR ALL PCBS" at 11448.46,2163.77 h60
  text "TO MEET OR EXCEED THE REQUIREMENTS OF:" at 11448.46,2069.71 h60
  text "X" at 11085.97,1941.08 h60
  text "ANSI IPC-A-600F CLASS ->" at 11213.96,1941.08 h60
  text "X" at 12861.97,1941.08 h60
  text "2" at 12971.96,1941.08 h60
  text "1" at 12656.96,1939.58 h60
  text "3" at 13325.96,1939.58 h60
  text "X" at 11897.97,1793.39 h60
  text "RoHS" at 12025.96,1793.39 h60
  text "OTHER" at 12670.36,1793.39 h60
  text "PER ORDER" at 13067.42,1793.39 h60
  text "ALL BOARDS MUST MEET OR EXCEED UL94-V0 REQUIREMENTS." at 10751,1639.57 h60
  text "PCB MUST BEAR THE UL94V-0 UL REGISTERED MATERIAL ID NUMBER" at 10751,1523.5 h60
  text "ADDITIONAL REQUIREMENTS:" at 10723.46,1354.08 h60
  text "MICROSECTION:" at 10798.23,1246.95 h60
  text "YES" at 11703.96,1246.95 h60
  text "REQUIRED" at 12565.46,1102.62 h60
  text "BARE BOARD ELEC. TEST:" at 10798.23,1099.76 h60
  text "NONE" at 12103.96,1099.76 h60
  text "X" at 13040,1100 h60
  text "PER ORDER" at 13157.46,1099.76 h60
  text "XX MIL VIAS REQUIRE NON-CONDUCTIVE FILL AND PLANARIZE" at 10966.38,894.82 h59
  text "XX MIL VIAS REQUIRE CONDUCTIVE FILL AND PLANARIZE" at 10974.38,790.84 h60
  text "OUTER XX MIL TRACES REQUIRE 50 OHM SINGLE-ENDED IMPEDANCE" at 10973.39,627.46 h58
  text "LAYER 2 & 3 (INNER LAYERS) XX MIL WIDE, XX MIL SPACE / TRACES REQUIRE 100 OHM DIFFERENTIAL IMPEDANCE" at 10965.39,391.74 h60
  text ".Layer_Name" at -33,-1358.49 h60
M11 Gerber Information:
  lines w10: -902,-1430.17 5698,-1430.17 ; -902,-1226.83 5700,-1226.83 ; -902,-1023.5 -902,-1633.5 3103,-1633.5 5700,-1633.5 5700,-1023.5 -901.5,-1023.5 -901.5,-1633.5 674,-1633.5 ; 1563,-1633.5 1563,-1023.5 ; 2830,-1226.83 2830,-1023.5 ; 3670,-1226.83 3670,-1023.5 ; 4292,-1640 4292,-1437.17
  text "ALL ARTWORK VIEWED FROM TOP SIDE" at -838.5,-1155.67 h60
  text "BOARD #:" at 1638,-1155.67 h60
  text ".PRJ_Number" at 2183.5,-1155.67 h60
  text "REV:" at 3028,-1155.67 h60
  text ".PCB_Rev" at 3319.5,-1155.67 h60
  text "SVN REV:" at 3866,-1155.67 h60
  text ".VersionControl_RevNumber" at 4372,-1155.67 h60
  text "LAYER NAME =" at -838.5,-1358.49 h60
  text "TID #:" at 1638,-1359 h60
  text ".TID" at 2183.5,-1359 h60
  text "PLOT NAME =" at -838.5,-1564.34 h60
  text ".plot_File_Name" at -33,-1564.34 h60
  text "GENERATED    :" at 1640,-1564.34 h60
  text ".Print_Date" at 2509.5,-1564.34 h60
  text ".Print_Time" at 3238.5,-1564.34 h60
  text "TEXAS INSTRUMENTS" at 4503,-1564.34 h60
M12 Stackup:
  drawing of 295 lines, arcs and shapes, not listed
  text "Layer" at 9187.84,7330 h60
  text "Name" at 9597.76,7330 h60
  text "Material" at 10537.5,7330 h60
  text "Thickness" at 11397.26,7330 h60
  text "Constant" at 12047.1,7330 h60
  text "Board Layer Stack" at 12616.96,7330 h60
  text "1" at 9187.84,7210 h60
  text "Top Overlay" at 9597.76,7210 h60
  text "2" at 9187.84,7090 h60
  text "Top Solder" at 9597.76,7090 h60
  text "Solder Resist" at 10537.5,7090 h60
  text "0.40mil" at 11397.26,7090 h60
  text "3.5" at 12047.1,7090 h60
  text "3" at 9187.84,6970 h60
  text "Top Layer" at 9597.76,6970 h60
  text "Copper" at 10537.5,6970 h60
  text "1.40mil" at 11397.26,6970 h60
  text "4" at 9187.84,6850 h60
  text "Dielectric 1" at 9597.76,6850 h60
  text "FR-4" at 10537.5,6850 h60
  text "12.00mil" at 11397.26,6850 h60
  text "4.2" at 12047.1,6850 h60
  text "5" at 9187.84,6730 h60
  text "Signal Layer 1" at 9597.76,6730 h60
  text "Copper" at 10537.5,6730 h60
  text "1.40mil" at 11397.26,6730 h60
  text "6" at 9187.84,6610 h60
  text "Dielectric 2" at 9597.76,6610 h60
  text "FR-4" at 10537.5,6610 h60
  text "31.00mil" at 11397.26,6610 h60
  text "4.2" at 12047.1,6610 h60
  text "7" at 9187.84,6490 h60
  text "Signal Layer 2" at 9597.76,6490 h60
  text "Copper" at 10537.5,6490 h60
  text "1.40mil" at 11397.26,6490 h60
  text "8" at 9187.84,6370 h60
  text "Dielectric 3" at 9597.76,6370 h60
  text "FR-4" at 10537.5,6370 h60
  text "12.00mil" at 11397.26,6370 h60
  text "4.2" at 12047.1,6370 h60
  text "9" at 9187.84,6250 h60
  text "Bottom Layer" at 9597.76,6250 h60
  text "Copper" at 10537.5,6250 h60
  text "1.40mil" at 11397.26,6250 h60
  text "10" at 9187.84,6130 h60
  text "Bottom Solder" at 9597.76,6130 h60
  text "Solder Resist" at 10537.5,6130 h60
  text "0.40mil" at 11397.26,6130 h60
  text "3.5" at 12047.1,6130 h60
  text "11" at 9187.84,6010 h60
  text "Bottom Overlay" at 9597.76,6010 h60
  text ".Layer_Name" at -33,-1358.49 h60
M13 Component Bodies Top:
  text ".Layer_Name" at -33,-1358.49 h60
M14 Component Bodies Bottom:
  text ".Layer_Name" at -33,-1358.49 h60
M15 Courtyards Top:
  text ".Layer_Name" at -33,-1358.49 h60
M16 Courtyards Bottom:
  text ".Layer_Name" at -33,-1358.49 h60
Drill Drawing:
  circle w10: c5756.72,2911 r27.63
  lines w10: 5729.09,3007.7 5784.34,3007.7 5784.34,3062.95 5729.09,3062.95 5729.09,3007.7 ; 5729.09,3145.83 5742.9,3145.83 5756.72,3132.02 5770.53,3145.83 5784.34,3145.83 5770.53,3159.64 5784.34,3173.46 5770.53,3173.46 5756.72,3187.27 5742.9,3173.46 5729.09,3173.46 5742.9,3159.64 5729.09,3145.83 ; 5729.09,3256.34 5756.72,3270.15 5784.34,3256.34 5770.53,3283.96 5784.34,3311.59 5756.72,3297.78 5729.09,3311.59 5742.9,3283.96 5729.09,3256.34 ; 5729.09,3435.91 5784.34,3435.91 5756.72,3380.66 5729.09,3435.91
  lines w12: 5679,2846.08 8910.49,2846.08 ; 5679,3467.68 8910.49,3467.68 ; 6016.86,2721.76 6016.86,3592 ; 6348.86,2721.76 6348.86,3592 ; 6985.43,2721.76 6985.43,3592 ; 7244.57,2721.76 7244.57,3592 ; 7619.72,2721.76 7619.72,3592 ; 8344.05,2721.76 8344.05,3592 ; 5679,2721.76 8910.49,2721.76 8910.49,3592 5679,3592 5679,2721.76
  text "Symbol" at 5753.59,3504.98 h72
  text "Quantity" at 6054.16,3504.98 h72
  text "Finished Hole Size" at 6386.16,3504.98 h72
  text "Plated" at 7022.72,3504.98 h72
  text "Hole Type" at 7281.86,3504.98 h72
  text "Drill Layer Pair" at 7657.02,3504.98 h72
  text "Hole Tolerance" at 8381.35,3504.98 h72
  text "169" at 6054.16,3380.66 h60
  text "7.87mil (0.200mm)" at 6386.16,3380.66 h60
  text "PTH" at 7022.72,3380.66 h60
  text "Round" at 7281.86,3380.66 h60
  text "Top Layer - Bottom Layer" at 7657.02,3380.66 h60
  text "45" at 6054.16,3256.34 h60
  text "10.00mil (0.254mm)" at 6386.16,3256.34 h60
  text "PTH" at 7022.72,3256.34 h60
  text "Round" at 7281.86,3256.34 h60
  text "Top Layer - Bottom Layer" at 7657.02,3256.34 h60
  text "156" at 6054.16,3132.02 h60
  text "15.00mil (0.381mm)" at 6386.16,3132.02 h60
  text "PTH" at 7022.72,3132.02 h60
  text "Round" at 7281.86,3132.02 h60
  text "Top Layer - Bottom Layer" at 7657.02,3132.02 h60
  text "4" at 6054.16,3007.7 h60
  text "125.98mil (3.200mm)" at 6386.16,3007.7 h60
  text "PTH" at 7022.72,3007.7 h60
  text "Round" at 7281.86,3007.7 h60
  text "Top Layer - Bottom Layer" at 7657.02,3007.7 h60
  text "6" at 6054.16,2883.38 h60
  text "144.00mil (3.658mm)" at 6386.16,2883.38 h60
  text "PTH" at 7022.72,2883.38 h60
  text "Round" at 7281.86,2883.38 h60
  text "Top Layer - Bottom Layer" at 7657.02,2883.38 h60
  text "380 Total" at 6054.16,2759.06 h60
  text ".Layer_Name" at -33,-1358.49 h60
M17 Embedded Cavity:
  text ".Layer_Name" at -33,-1358.49 h60
M18 Embedded Assembly:
  text ".Layer_Name" at -33,-1358.49 h60
M19 Embedded Keepout:
  text ".Layer_Name" at -33,-1358.49 h60

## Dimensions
0,0 to 4470,0 on M2 Board Dimensions
0,0 to 0,3145 on M2 Board Dimensions
-610,-900 to 390,-900 on M2 Board Dimensions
